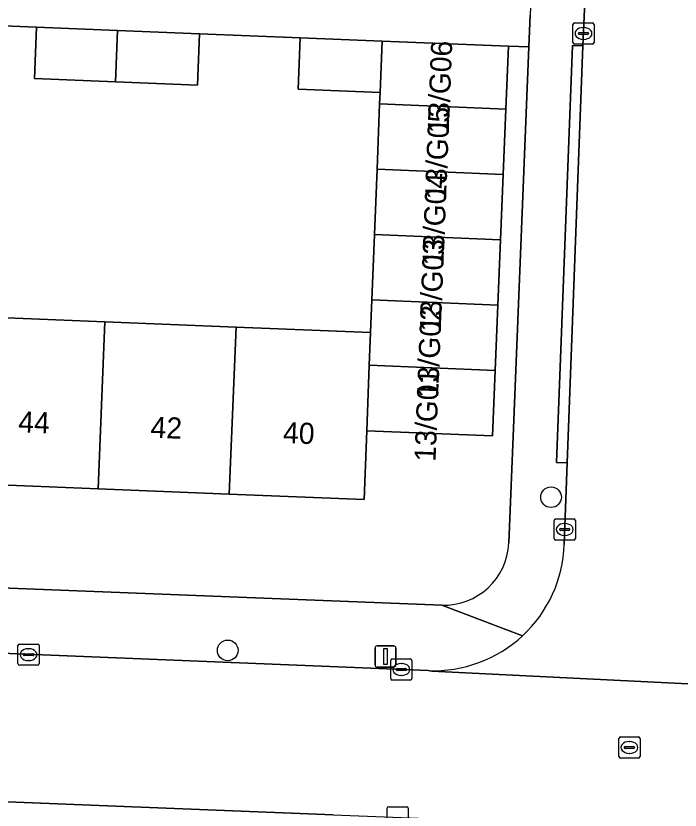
# Model space of a CAD drawing. Extents: x 161354 to 162026, y 386504 to 387460.
# Drawn here: x 161583.62 to 161615.02, y 386647.05 to 386684.61 of the extents above; entities that cross this region are included whole.
import ezdxf

# ---------------------------------------------------------------- set-up
doc = ezdxf.new("R2010")
doc.units = 0
for name, color, linetype in [('IMGEO_Boom', 7, 'Continuous'), ('IMGEO_Erf', 7, 'Continuous'), ('IMGEO_Kolk', 7, 'Continuous'), ('IMGEO_Lichtmast', 7, 'Continuous'), ('IMGEO_Pand', 7, 'Continuous'), ('IMGEO_Pand_nummerreeks', 7, 'Continuous'), ('IMGEO_Parkeervlak_open', 7, 'Continuous'), ('IMGEO_Rijbaan_lokaal_open', 7, 'Continuous'), ('IMGEO_Rioolput', 7, 'Continuous'), ('IMGEO_Voetpad_open', 7, 'Continuous')]:
    doc.layers.add(name, color=color, linetype=linetype)

msp = doc.modelspace()

# ---------------------------------------------------------------- linework, layer by layer
at = {"layer": 'IMGEO_Boom'}
for centre in [(161608.916, 386661.853), (161593.632, 386654.609)]:
    msp.add_circle(centre, 0.489, dxfattribs=at)
at = {"layer": 'IMGEO_Erf'}
for points in [[(161600.439, 386671.181), (161600.564, 386674.271), (161600.69, 386677.362), (161600.815, 386680.453), (161600.837, 386680.997), (161596.965, 386681.153), (161597.063, 386683.581), (161592.301, 386683.773), (161592.203, 386681.345), (161588.326, 386681.502), (161584.497, 386681.657), (161584.595, 386684.085), (161579.921, 386684.274), (161579.823, 386681.846), (161575.946, 386682.002), (161572.079, 386682.158), (161572.177, 386684.586), (161567.372, 386684.781), (161567.274, 386682.353), (161563.397, 386682.509), (161563.495, 386684.937), (161558.303, 386685.147), (161557.287, 386660.13)], [(161606.918, 386659.698), (161607.123, 386664.718), (161607.873, 386683.145), (161606.9, 386683.184), (161606.78, 386680.211), (161606.654, 386677.12), (161606.529, 386674.03), (161606.404, 386670.939), (161606.278, 386667.848), (161606.153, 386664.757), (161600.215, 386664.998), (161600.081, 386661.74), (161593.707, 386661.998), (161587.508, 386662.25), (161581.31, 386662.501)], [(161581.63, 386670.393), (161587.828, 386670.142), (161594.027, 386669.89), (161600.376, 386669.634), (161600.439, 386671.181)], [(161558.773, 386658.522), (161560.053, 386658.471), (161603.753, 386656.748)]]:
    msp.add_lwpolyline(points, dxfattribs=at)
msp.add_arc((161603.852, 386659.814), 3.068, 268.1449, 357.8278, dxfattribs=at)
at = {"layer": 'IMGEO_Kolk'}
for p, q in [((161610.025, 386684.284), (161610.877, 386684.284)), ((161609.95, 386683.358), (161609.95, 386684.21)), ((161610.438, 386684.064), (161610.463, 386684.064)), ((161610.951, 386684.21), (161610.951, 386683.358)), ((161610.209, 386683.778), (161610.209, 386683.79)), ((161610.647, 386683.741), (161610.249, 386683.741)), ((161610.252, 386683.827), (161610.65, 386683.827)), ((161610.461, 386683.504), (161610.436, 386683.504)), ((161610.693, 386683.79), (161610.693, 386683.778)), ((161610.877, 386683.284), (161610.025, 386683.284)), ((161609.065, 386659.901), (161609.065, 386660.753)), ((161609.14, 386660.827), (161609.992, 386660.827)), ((161609.553, 386660.607), (161609.578, 386660.607)), ((161610.066, 386660.753), (161610.066, 386659.901)), ((161609.324, 386660.321), (161609.324, 386660.333)), ((161609.762, 386660.284), (161609.364, 386660.284)), ((161609.367, 386660.37), (161609.765, 386660.37)), ((161609.808, 386660.333), (161609.808, 386660.321)), ((161609.576, 386660.047), (161609.551, 386660.047)), ((161609.992, 386659.827), (161609.14, 386659.827)), ((161583.716, 386653.981), (161583.716, 386654.833)), ((161583.791, 386654.907), (161584.643, 386654.907)), ((161584.204, 386654.687), (161584.229, 386654.687)), ((161584.717, 386654.833), (161584.717, 386653.981)), ((161583.975, 386654.401), (161583.975, 386654.413)), ((161584.413, 386654.364), (161584.015, 386654.364)), ((161584.018, 386654.45), (161584.416, 386654.45)), ((161584.459, 386654.413), (161584.459, 386654.401)), ((161601.413, 386654.205), (161602.265, 386654.205)), ((161584.643, 386653.907), (161583.791, 386653.907)), ((161584.227, 386654.127), (161584.202, 386654.127)), ((161601.338, 386653.279), (161601.338, 386654.131)), ((161601.826, 386653.985), (161601.851, 386653.985)), ((161602.339, 386654.131), (161602.339, 386653.279)), ((161601.597, 386653.699), (161601.597, 386653.711)), ((161602.035, 386653.662), (161601.637, 386653.662)), ((161601.64, 386653.748), (161602.038, 386653.748)), ((161602.081, 386653.711), (161602.081, 386653.699)), ((161602.265, 386653.205), (161601.413, 386653.205)), ((161601.849, 386653.425), (161601.824, 386653.425)), ((161601.166, 386646.29), (161601.166, 386647.142)), ((161601.241, 386647.216), (161602.093, 386647.216)), ((161602.167, 386647.142), (161602.167, 386646.29))]:
    msp.add_line(p, q, dxfattribs=at)
for points in [[(161610.025, 386684.284), (161610.877, 386684.284)], [(161609.95, 386683.358), (161609.95, 386684.21)], [(161610.951, 386684.21), (161610.951, 386683.358)], [(161610.877, 386683.284), (161610.025, 386683.284)], [(161609.065, 386659.901), (161609.065, 386660.753)], [(161609.14, 386660.827), (161609.992, 386660.827)], [(161610.066, 386660.753), (161610.066, 386659.901)], [(161609.992, 386659.827), (161609.14, 386659.827)], [(161583.716, 386653.981), (161583.716, 386654.833)], [(161583.791, 386654.907), (161584.643, 386654.907)], [(161584.717, 386654.833), (161584.717, 386653.981)], [(161601.413, 386654.205), (161602.265, 386654.205)], [(161584.643, 386653.907), (161583.791, 386653.907)], [(161601.338, 386653.279), (161601.338, 386654.131)], [(161602.339, 386654.131), (161602.339, 386653.279)], [(161602.265, 386653.205), (161601.413, 386653.205)], [(161601.166, 386646.29), (161601.166, 386647.142)], [(161601.241, 386647.216), (161602.093, 386647.216)], [(161602.167, 386647.142), (161602.167, 386646.29)]]:
    msp.add_lwpolyline(points, dxfattribs=at)
for centre, radius, start, end in [((161610.027, 386684.208), 0.0765, 91.552, 178.448), ((161610.027, 386684.208), 0.0765, 91.552, 178.448), ((161610.875, 386684.208), 0.0765, 1.552, 88.448), ((161610.875, 386684.208), 0.0765, 1.552, 88.448), ((161610.249, 386683.787), 0.0403, 85.8775, 175.7526), ((161610.246, 386683.777), 0.0366, 178.938, 274.7102), ((161610.65, 386683.784), 0.043, 264.8664, 352.4533), ((161610.654, 386683.789), 0.0386, 1.7309, 96.639), ((161610.027, 386683.36), 0.0765, 181.552, 268.448), ((161610.027, 386683.36), 0.0765, 181.552, 268.448), ((161610.875, 386683.36), 0.0765, 271.552, 358.448), ((161610.875, 386683.36), 0.0765, 271.552, 358.448), ((161609.142, 386660.751), 0.0765, 91.552, 178.448), ((161609.142, 386660.751), 0.0765, 91.552, 178.448), ((161609.99, 386660.751), 0.0765, 1.552, 88.448), ((161609.99, 386660.751), 0.0765, 1.552, 88.448), ((161609.364, 386660.33), 0.0403, 85.8775, 175.7526), ((161609.361, 386660.32), 0.0366, 178.938, 274.7102), ((161609.765, 386660.327), 0.043, 264.8664, 352.4533), ((161609.769, 386660.332), 0.0386, 1.7309, 96.639), ((161609.142, 386659.903), 0.0765, 181.552, 268.448), ((161609.142, 386659.903), 0.0765, 181.552, 268.448), ((161609.99, 386659.903), 0.0765, 271.552, 358.448), ((161609.99, 386659.903), 0.0765, 271.552, 358.448), ((161583.793, 386654.831), 0.0765, 91.552, 178.448), ((161583.793, 386654.831), 0.0765, 91.552, 178.448), ((161584.641, 386654.831), 0.0765, 1.552, 88.448), ((161584.641, 386654.831), 0.0765, 1.552, 88.448), ((161584.015, 386654.41), 0.0403, 85.8775, 175.7526), ((161584.012, 386654.4), 0.0366, 178.938, 274.7102), ((161584.416, 386654.407), 0.043, 264.8664, 352.4533), ((161584.42, 386654.412), 0.0386, 1.7309, 96.639), ((161601.415, 386654.129), 0.0765, 91.552, 178.448), ((161601.415, 386654.129), 0.0765, 91.552, 178.448), ((161602.263, 386654.129), 0.0765, 1.552, 88.448), ((161602.263, 386654.129), 0.0765, 1.552, 88.448), ((161583.793, 386653.983), 0.0765, 181.552, 268.448), ((161583.793, 386653.983), 0.0765, 181.552, 268.448), ((161584.641, 386653.983), 0.0765, 271.552, 358.448), ((161584.641, 386653.983), 0.0765, 271.552, 358.448), ((161601.637, 386653.708), 0.0403, 85.8775, 175.7526), ((161601.634, 386653.698), 0.0366, 178.938, 274.7102), ((161602.038, 386653.705), 0.043, 264.8664, 352.4533), ((161602.042, 386653.71), 0.0386, 1.7309, 96.639), ((161601.415, 386653.281), 0.0765, 181.552, 268.448), ((161601.415, 386653.281), 0.0765, 181.552, 268.448), ((161602.263, 386653.281), 0.0765, 271.552, 358.448), ((161602.263, 386653.281), 0.0765, 271.552, 358.448), ((161601.243, 386647.14), 0.0765, 91.552, 178.448), ((161601.243, 386647.14), 0.0765, 91.552, 178.448), ((161602.091, 386647.14), 0.0765, 1.552, 88.448), ((161602.091, 386647.14), 0.0765, 1.552, 88.448)]:
    msp.add_arc(centre, radius, start, end, dxfattribs=at)
for centre, major_axis, ratio, start_param, end_param in [((161610.437, 386683.784), (-0.387, 0.002), 0.722429, 4.712389, 7.853982), ((161610.462, 386683.784), (-0.39, 0.002), 0.717154, 1.570796, 4.712389), ((161609.552, 386660.327), (-0.387, 0.002), 0.722429, 4.712389, 7.853982), ((161609.577, 386660.327), (-0.39, 0.002), 0.717154, 1.570796, 4.712389), ((161584.203, 386654.407), (-0.387, 0.002), 0.722429, 4.712389, 7.853982), ((161584.228, 386654.407), (-0.39, 0.002), 0.717154, 1.570796, 4.712389), ((161601.825, 386653.705), (-0.387, 0.002), 0.722429, 4.712389, 7.853982), ((161601.85, 386653.705), (-0.39, 0.002), 0.717154, 1.570796, 4.712389)]:
    msp.add_ellipse(centre, major_axis=major_axis, ratio=ratio, start_param=start_param, end_param=end_param, dxfattribs=at)
at = {"layer": 'IMGEO_Lichtmast'}
for p, q in [((161600.595, 386653.921), (161600.595, 386654.721)), ((161600.595, 386654.721), (161600.595, 386653.921)), ((161600.695, 386654.821), (161601.485, 386654.821)), ((161601.485, 386654.821), (161600.695, 386654.821)), ((161601.585, 386654.721), (161601.585, 386653.921)), ((161601.585, 386653.921), (161601.585, 386654.721)), ((161601.485, 386653.821), (161600.695, 386653.821)), ((161600.695, 386653.821), (161601.485, 386653.821))]:
    msp.add_line(p, q, dxfattribs=at)
msp.add_lwpolyline([(161601.015, 386654.696), (161601.165, 386654.696), (161601.165, 386653.946), (161601.015, 386653.946), (161601.015, 386654.696)], dxfattribs=at)
for centre, start, end in [((161600.695, 386654.721), 90, 180), ((161600.695, 386654.721), 90, 180), ((161601.485, 386654.721), 0, 90), ((161601.485, 386654.721), 360, 90), ((161600.695, 386653.921), 180, 270), ((161600.695, 386653.921), 180, 270), ((161601.485, 386653.921), 270, 0), ((161601.485, 386653.921), 270, 0)]:
    msp.add_arc(centre, 0.1, start, end, dxfattribs=at)
at = {"layer": 'IMGEO_Pand'}
for points in [[(161588.424, 386683.93), (161584.595, 386684.085), (161584.497, 386681.657), (161588.326, 386681.502)], [(161592.301, 386683.773), (161588.424, 386683.93), (161588.326, 386681.502), (161592.203, 386681.345)], [(161600.94, 386683.424), (161597.063, 386683.581), (161596.965, 386681.153), (161600.837, 386680.997)], [(161606.9, 386683.184), (161600.94, 386683.424), (161600.837, 386680.997), (161600.815, 386680.453), (161606.78, 386680.211)], [(161600.815, 386680.453), (161600.69, 386677.362), (161606.654, 386677.12), (161606.78, 386680.211)], [(161606.529, 386674.03), (161606.654, 386677.12), (161600.69, 386677.362), (161600.564, 386674.271)], [(161600.564, 386674.271), (161600.439, 386671.181), (161606.404, 386670.939), (161606.529, 386674.03)], [(161600.439, 386671.181), (161600.376, 386669.634), (161600.322, 386668.089), (161606.278, 386667.848), (161606.404, 386670.939)], [(161587.828, 386670.142), (161581.63, 386670.393), (161581.31, 386662.501), (161587.508, 386662.25)], [(161594.027, 386669.89), (161587.828, 386670.142), (161587.508, 386662.25), (161593.707, 386661.998)], [(161600.322, 386668.089), (161600.376, 386669.634), (161594.027, 386669.89), (161593.707, 386661.998), (161600.081, 386661.74), (161600.215, 386664.998)], [(161606.153, 386664.757), (161606.278, 386667.848), (161600.322, 386668.089), (161600.215, 386664.998)]]:
    msp.add_lwpolyline(points, close=True, dxfattribs=at)
at = {"layer": 'IMGEO_Parkeervlak_open'}
msp.add_lwpolyline([(161598.62, 386646.837), (161574.112, 386647.814), (161574.028, 386645.756), (161581.474, 386645.461), (161595.594, 386644.882)], dxfattribs=at)
at = {"layer": 'IMGEO_Rijbaan_lokaal_open'}
for points in [[(161617.932, 386696.807), (161618.646, 386712.528), (161611.678, 386712.667), (161611.078, 386697.711), (161610.426, 386683.2), (161609.675, 386663.473), (161609.543, 386659.62)], [(161603.115, 386653.653), (161603.283, 386653.631), (161621.456, 386652.727), (161621.808, 386652.733)]]:
    msp.add_lwpolyline(points, dxfattribs=at)
msp.add_lwpolyline([(161648.537, 386651.647), (161621.808, 386652.733), (161621.456, 386652.727), (161603.283, 386653.631), (161603.115, 386653.653), (161574.397, 386654.821), (161574.112, 386647.814), (161598.62, 386646.837), (161603.06, 386646.66), (161603.365, 386646.67), (161621.292, 386645.742), (161648.332, 386644.685)], close=True, dxfattribs=at)
for centre, radius, start, end in [((161603.366, 386659.831), 6.181, 312.8602, 358.0462), ((161603.362, 386659.835), 6.187, 267.7161, 312.8623)]:
    msp.add_arc(centre, radius, start, end, dxfattribs=at)
at = {"layer": 'IMGEO_Rioolput'}
for p, q in [((161612.123, 386649.592), (161612.123, 386650.444)), ((161612.198, 386650.518), (161613.05, 386650.518)), ((161613.124, 386650.444), (161613.124, 386649.592)), ((161612.611, 386650.298), (161612.636, 386650.298)), ((161612.382, 386650.012), (161612.382, 386650.024)), ((161612.82, 386649.975), (161612.422, 386649.975)), ((161612.425, 386650.061), (161612.823, 386650.061)), ((161612.634, 386649.738), (161612.609, 386649.738)), ((161612.866, 386650.024), (161612.866, 386650.012)), ((161613.05, 386649.518), (161612.198, 386649.518))]:
    msp.add_line(p, q, dxfattribs=at)
for points in [[(161612.123, 386649.592), (161612.123, 386650.444)], [(161612.198, 386650.518), (161613.05, 386650.518)], [(161613.124, 386650.444), (161613.124, 386649.592)], [(161613.05, 386649.518), (161612.198, 386649.518)]]:
    msp.add_lwpolyline(points, dxfattribs=at)
for centre, radius, start, end in [((161612.2, 386650.442), 0.0765, 91.552, 178.448), ((161612.2, 386650.442), 0.0765, 91.552, 178.448), ((161613.048, 386650.442), 0.0765, 1.552, 88.448), ((161613.048, 386650.442), 0.0765, 1.552, 88.448), ((161612.422, 386650.021), 0.0403, 85.8775, 175.7526), ((161612.419, 386650.011), 0.0366, 178.938, 274.7102), ((161612.823, 386650.018), 0.043, 264.8664, 352.4533), ((161612.827, 386650.023), 0.0386, 1.7309, 96.639), ((161612.2, 386649.594), 0.0765, 181.552, 268.448), ((161612.2, 386649.594), 0.0765, 181.552, 268.448), ((161613.048, 386649.594), 0.0765, 271.552, 358.448), ((161613.048, 386649.594), 0.0765, 271.552, 358.448)]:
    msp.add_arc(centre, radius, start, end, dxfattribs=at)
for centre, major_axis, ratio, start_param, end_param in [((161612.61, 386650.018), (-0.387, 0.002), 0.722429, 4.712389, 7.853982), ((161612.635, 386650.018), (-0.39, 0.002), 0.717154, 1.570796, 4.712389)]:
    msp.add_ellipse(centre, major_axis=major_axis, ratio=ratio, start_param=start_param, end_param=end_param, dxfattribs=at)
at = {"layer": 'IMGEO_Voetpad_open'}
for points in [[(161611.678, 386712.667), (161611.793, 386715.557), (161612.103, 386723.261), (161611.604, 386723.281), (161612.391, 386742.904), (161612.89, 386742.884), (161613.15, 386749.371), (161610.513, 386749.488), (161610.273, 386742.389), (161609.081, 386742.497), (161608.959, 386739.384), (161608.837, 386736.271), (161608.715, 386733.158), (161608.593, 386730.044), (161608.471, 386726.931), (161608.349, 386723.818), (161608.339, 386723.566), (161609.523, 386723.517), (161609.457, 386722.018), (161607.934, 386684.643), (161607.873, 386683.145), (161607.123, 386664.718), (161606.918, 386659.698)], [(161609.543, 386659.62), (161609.675, 386663.473), (161609.176, 386663.491), (161609.927, 386683.218), (161610.426, 386683.2), (161611.078, 386697.711), (161611.678, 386712.667)], [(161567.372, 386684.781), (161572.177, 386684.586), (161576.044, 386684.43), (161579.921, 386684.274), (161584.595, 386684.085), (161588.424, 386683.93), (161592.301, 386683.773), (161597.063, 386683.581), (161600.94, 386683.424), (161606.9, 386683.184), (161607.873, 386683.145), (161607.934, 386684.643)], [(161603.753, 386656.748), (161560.053, 386658.471), (161559.908, 386655.41), (161571.589, 386654.935), (161574.397, 386654.821), (161603.115, 386653.653)], [(161607.57, 386655.3), (161603.753, 386656.748)], [(161603.753, 386656.748), (161607.57, 386655.3)]]:
    msp.add_lwpolyline(points, dxfattribs=at)
msp.add_lwpolyline([(161610.426, 386683.2), (161609.927, 386683.218), (161609.176, 386663.491), (161609.675, 386663.473)], close=True, dxfattribs=at)
for centre, radius, start, end in [((161603.852, 386659.814), 3.068, 268.1449, 357.8278), ((161603.366, 386659.831), 6.181, 312.8602, 358.0462), ((161603.362, 386659.835), 6.187, 267.7161, 312.8623)]:
    msp.add_arc(centre, radius, start, end, dxfattribs=at)

# ---------------------------------------------------------------- texts
at = {"layer": 'IMGEO_Pand_nummerreeks'}
for s, rotation, p in [('13/G06', 87.7084, (161604.076, 386679.036)), ('13/G05', 87.7094, (161603.951, 386675.911)), ('13/G04', 87.7094, (161603.826, 386672.786)), ('13/G03', 87.7094, (161603.701, 386669.661)), ('13/G02', 87.7094, (161603.576, 386666.529)), ('13/G01', 87.7094, (161603.455, 386663.521)), ('44', 357.6784, (161583.715, 386664.926)), ('42', 357.6784, (161589.969, 386664.672)), ('40', 357.6784, (161596.232, 386664.418))]:
    msp.add_text(s, height=1, rotation=rotation, dxfattribs=at).set_placement(p)

doc.saveas('drawing.dxf')
